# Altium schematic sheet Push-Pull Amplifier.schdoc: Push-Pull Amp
size A4; Organization: Altium Limited; Address1: L3, 12a Rodborough Rd; Address2: Frenchs Forest; Address3: NSW; Address4: Australia 2086; DocumentNumber: 1; SheetNumber: 1; SheetTotal: 1
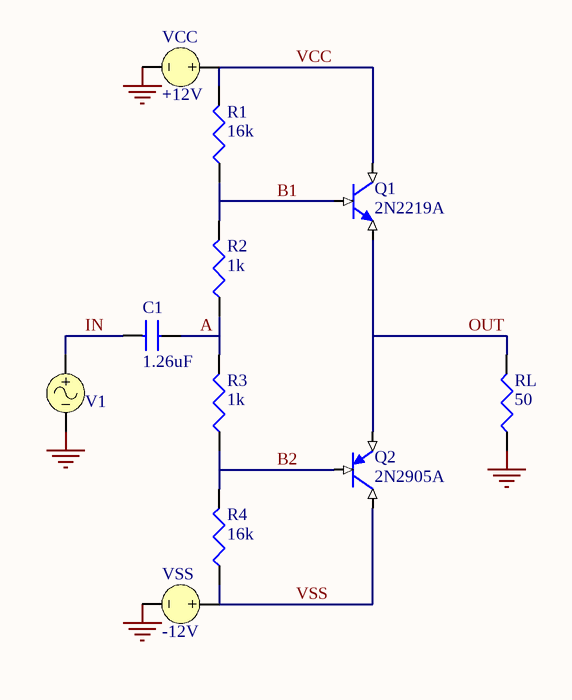
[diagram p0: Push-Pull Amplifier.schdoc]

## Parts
C1  1.26uF
Q1  2N2219A
Q2  2N2905A
R1  16k
R2  1k
R3  1k
R4  16k
RL  50
V1  VSIN  (value not drawn)
VCC  +12V
VSS  -12V

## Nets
GND: RL.2(BOT) V1.2 VCC.2 VSS.2
A: C1.2 R2.2(BOT) R3.1(TOP)
B1: Q1.2(B) R1.2(BOT) R2.1(TOP)
B2: Q2.2(B) R3.2(BOT) R4.1(TOP)
IN: C1.1 V1.1
OUT: Q1.3(E) Q2.3(E) RL.1(TOP)
VCC: Q1.1(C) R1.1(TOP) VCC.1
VSS: Q2.1(C) R4.2(BOT) VSS.1

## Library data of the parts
C1 = CAP: Capacitor
Q1 = 2N2219A: NPN BJT
Q2 = 2N2905A: PNP BJT
R1-R4 RL = RES: Resistor
V1 = VSIN: Sinusoidal Voltage Source
VCC VSS = VSRC: Voltage Source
